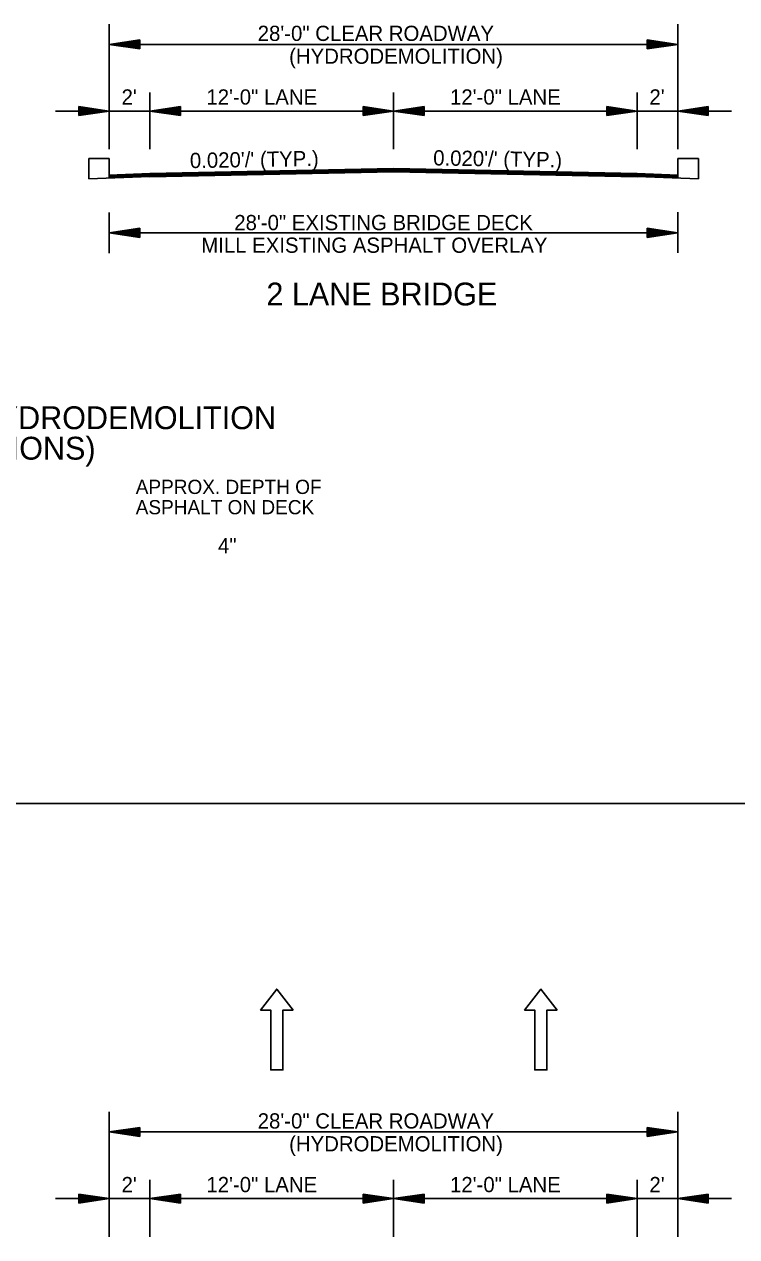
# Model space of a CAD drawing. Extents: x 549600 to 1930787, y -1955432 to 596640.
# Drawn here: x 551680 to 552031, y -1952647 to -1952050 of the extents above; entities that cross this region are included whole.
import ezdxf

# ---------------------------------------------------------------- set-up
doc = ezdxf.new("R2010")
doc.units = 0
for name, color, linetype in [('R_Border', 7, 'Continuous'), ('R_Border Notes', 7, 'Continuous'), ('S_AREA_CALC', 7, 'Continuous')]:
    doc.layers.add(name, color=color, linetype=linetype)

msp = doc.modelspace()

# ---------------------------------------------------------------- linework, layer by layer
at = {"layer": 'R_Border'}
for p, q in [((551711.85, -1952115.83), (551711.85, -1952125.95)), ((551722.02, -1952115.83), (551711.85, -1952115.83)), ((551722.02, -1952125.24), (551722.02, -1952115.83)), ((552002.02, -1952125.24), (552002.02, -1952115.83)), ((552002.02, -1952115.83), (552012.18, -1952115.83)), ((552012.18, -1952115.83), (552012.18, -1952125.95)), ((551008.97, -1952433.38), (552070.24, -1952433.38))]:
    msp.add_line(p, q, dxfattribs=at)
for points in [[(551812.52, -1952535.08), (551804.52, -1952524.69), (551796.52, -1952535.08), (551801.52, -1952535.08), (551801.52, -1952564.5), (551807.52, -1952564.5), (551807.52, -1952535.08)], [(551942.58, -1952535.08), (551934.58, -1952524.69), (551926.58, -1952535.08), (551931.58, -1952535.08), (551931.58, -1952564.5), (551937.58, -1952564.5), (551937.58, -1952535.08)]]:
    msp.add_lwpolyline(points, close=True, dxfattribs=at)
at = {"layer": 'S_AREA_CALC'}
for p, q in [((551722.02, -1952111.3), (551722.02, -1952049.81)), ((552002.02, -1952111.3), (552002.02, -1952049.81)), ((551737.02, -1952057.45), (551722.02, -1952059.7)), ((552002.02, -1952059.7), (551722.02, -1952059.7)), ((551737.02, -1952061.95), (551722.02, -1952059.7)), ((551737.02, -1952057.82), (551724.52, -1952059.7)), ((551737.02, -1952061.57), (551724.52, -1952059.7)), ((551737.02, -1952058.21), (551727.1, -1952059.7)), ((551737.02, -1952061.19), (551727.1, -1952059.7)), ((551737.02, -1952058.58), (551729.6, -1952059.7)), ((551737.02, -1952060.82), (551729.6, -1952059.7)), ((551737.02, -1952058.97), (551732.14, -1952059.7)), ((551737.02, -1952060.43), (551732.14, -1952059.7)), ((551737.02, -1952059.35), (551734.65, -1952059.7)), ((551737.02, -1952060.05), (551734.65, -1952059.7)), ((551737.02, -1952057.45), (551737.02, -1952061.95)), ((551987.02, -1952057.45), (552002.02, -1952059.7)), ((551987.02, -1952061.95), (551987.02, -1952057.45)), ((551987.02, -1952057.82), (551999.51, -1952059.7)), ((551987.02, -1952058.21), (551996.93, -1952059.7)), ((551987.02, -1952058.58), (551994.44, -1952059.7)), ((551987.02, -1952058.96), (551991.89, -1952059.7)), ((551987.02, -1952059.35), (551989.39, -1952059.7)), ((551987.02, -1952061.95), (552002.02, -1952059.7)), ((551987.02, -1952060.43), (551991.89, -1952059.7)), ((551987.02, -1952061.19), (551996.93, -1952059.7)), ((551987.02, -1952061.57), (551999.51, -1952059.7)), ((551987.02, -1952060.82), (551994.44, -1952059.7)), ((551987.02, -1952060.05), (551989.39, -1952059.7)), ((551742.02, -1952111.3), (551742.02, -1952083.34)), ((551862.02, -1952111.3), (551862.02, -1952083.34)), ((551982.02, -1952111.3), (551982.02, -1952083.34)), ((551722.02, -1952092.53), (551695.5, -1952092.53)), ((551707.02, -1952090.28), (551722.02, -1952092.53)), ((551707.02, -1952090.28), (551707.02, -1952094.78)), ((551707.02, -1952090.66), (551719.51, -1952092.53)), ((551707.02, -1952091.04), (551716.93, -1952092.53)), ((551707.02, -1952091.42), (551714.44, -1952092.53)), ((551707.02, -1952091.81), (551711.89, -1952092.53)), ((551707.02, -1952092.18), (551709.39, -1952092.53)), ((551707.02, -1952094.78), (551722.02, -1952092.53)), ((551707.02, -1952093.27), (551711.89, -1952092.53)), ((551707.02, -1952094.03), (551716.93, -1952092.53)), ((551707.02, -1952094.41), (551719.51, -1952092.53)), ((551707.02, -1952093.65), (551714.44, -1952092.53)), ((551707.02, -1952092.89), (551709.39, -1952092.53)), ((551742.02, -1952092.53), (551722.02, -1952092.53)), ((551757.02, -1952090.28), (551742.02, -1952092.53)), ((551862.02, -1952092.53), (551742.02, -1952092.53)), ((551757.02, -1952094.78), (551742.02, -1952092.53)), ((551757.02, -1952090.66), (551744.52, -1952092.53)), ((551757.02, -1952094.41), (551744.52, -1952092.53)), ((551757.02, -1952091.04), (551747.1, -1952092.53)), ((551757.02, -1952094.03), (551747.1, -1952092.53)), ((551757.02, -1952091.42), (551749.6, -1952092.53)), ((551757.02, -1952093.65), (551749.6, -1952092.53)), ((551757.02, -1952091.81), (551752.14, -1952092.53)), ((551757.02, -1952093.27), (551752.14, -1952092.53)), ((551757.02, -1952092.18), (551754.65, -1952092.53)), ((551757.02, -1952092.89), (551754.65, -1952092.53)), ((551757.02, -1952090.28), (551757.02, -1952094.78)), ((551847.02, -1952090.28), (551862.02, -1952092.53)), ((551847.02, -1952090.28), (551847.02, -1952094.78)), ((551847.02, -1952090.66), (551859.51, -1952092.53)), ((551847.02, -1952091.04), (551856.93, -1952092.53)), ((551847.02, -1952091.42), (551854.44, -1952092.53)), ((551847.02, -1952091.81), (551851.89, -1952092.53)), ((551847.02, -1952092.18), (551849.39, -1952092.53)), ((551847.02, -1952094.78), (551862.02, -1952092.53)), ((551847.02, -1952093.27), (551851.89, -1952092.53)), ((551847.02, -1952094.03), (551856.93, -1952092.53)), ((551847.02, -1952094.41), (551859.51, -1952092.53)), ((551847.02, -1952093.65), (551854.44, -1952092.53)), ((551847.02, -1952092.89), (551849.39, -1952092.53)), ((551877.02, -1952090.28), (551862.02, -1952092.53)), ((551982.02, -1952092.53), (551862.02, -1952092.53)), ((551877.02, -1952094.78), (551862.02, -1952092.53)), ((551877.02, -1952090.66), (551864.52, -1952092.53)), ((551877.02, -1952094.41), (551864.52, -1952092.53)), ((551877.02, -1952091.04), (551867.1, -1952092.53)), ((551877.02, -1952094.03), (551867.1, -1952092.53)), ((551877.02, -1952091.42), (551869.6, -1952092.53)), ((551877.02, -1952093.65), (551869.6, -1952092.53)), ((551877.02, -1952091.81), (551872.14, -1952092.53)), ((551877.02, -1952093.27), (551872.14, -1952092.53)), ((551877.02, -1952092.18), (551874.65, -1952092.53)), ((551877.02, -1952092.89), (551874.65, -1952092.53)), ((551877.02, -1952090.28), (551877.02, -1952094.78)), ((551967.02, -1952090.28), (551982.02, -1952092.53)), ((551967.02, -1952090.28), (551967.02, -1952094.78)), ((551967.02, -1952090.66), (551979.51, -1952092.53)), ((551967.02, -1952091.04), (551976.93, -1952092.53)), ((551967.02, -1952091.42), (551974.44, -1952092.53)), ((551967.02, -1952091.81), (551971.89, -1952092.53)), ((551967.02, -1952092.18), (551969.39, -1952092.53)), ((551967.02, -1952094.78), (551982.02, -1952092.53)), ((551967.02, -1952093.27), (551971.89, -1952092.53)), ((551967.02, -1952094.03), (551976.93, -1952092.53)), ((551967.02, -1952094.41), (551979.51, -1952092.53)), ((551967.02, -1952093.65), (551974.44, -1952092.53)), ((551967.02, -1952092.89), (551969.39, -1952092.53)), ((551982.02, -1952092.53), (552002.02, -1952092.53)), ((552017.02, -1952090.28), (552002.02, -1952092.53)), ((552017.02, -1952094.78), (552002.02, -1952092.53)), ((552028.54, -1952092.53), (552002.02, -1952092.53)), ((552017.02, -1952090.66), (552004.52, -1952092.53)), ((552017.02, -1952094.41), (552004.52, -1952092.53)), ((552017.02, -1952091.04), (552007.1, -1952092.53)), ((552017.02, -1952094.03), (552007.1, -1952092.53)), ((552017.02, -1952091.42), (552009.6, -1952092.53)), ((552017.02, -1952093.65), (552009.6, -1952092.53)), ((552017.02, -1952091.81), (552012.14, -1952092.53)), ((552017.02, -1952093.27), (552012.14, -1952092.53)), ((552017.02, -1952092.18), (552014.65, -1952092.53)), ((552017.02, -1952092.89), (552014.65, -1952092.53)), ((552017.02, -1952090.28), (552017.02, -1952094.78)), ((551862.02, -1952120.84), (551742.02, -1952123.24)), ((551862.02, -1952121.14), (551742.02, -1952123.54)), ((551862.02, -1952121.44), (551742.02, -1952123.84)), ((551862.02, -1952121.74), (551742.02, -1952124.14)), ((551862.02, -1952122.04), (551742.02, -1952124.44)), ((551862.02, -1952122.34), (551742.02, -1952124.74)), ((551862.02, -1952122.51), (551742.02, -1952124.91)), ((551862.02, -1952120.84), (551982.02, -1952123.24)), ((551862.02, -1952121.14), (551982.02, -1952123.54)), ((551862.02, -1952121.44), (551982.02, -1952123.84)), ((551862.02, -1952121.74), (551982.02, -1952124.14)), ((551862.02, -1952122.04), (551982.02, -1952124.44)), ((551862.02, -1952122.34), (551982.02, -1952124.74)), ((551862.02, -1952122.51), (551982.02, -1952124.91)), ((551742.02, -1952124.74), (551711.85, -1952125.95)), ((551742.02, -1952123.24), (551722.02, -1952124.04)), ((551742.02, -1952123.54), (551722.02, -1952124.34)), ((551742.02, -1952123.84), (551722.02, -1952124.64)), ((551742.02, -1952124.14), (551722.02, -1952124.94)), ((551742.02, -1952124.44), (551722.02, -1952125.24)), ((551982.02, -1952123.24), (552002.02, -1952124.04)), ((551982.02, -1952123.54), (552002.02, -1952124.34)), ((551982.02, -1952123.84), (552002.02, -1952124.64)), ((551982.02, -1952124.14), (552002.02, -1952124.94)), ((551982.02, -1952124.44), (552002.02, -1952125.24)), ((551982.02, -1952124.74), (552012.18, -1952125.95)), ((551722.02, -1952142.5), (551722.02, -1952162.5)), ((552002.02, -1952142.25), (552002.02, -1952162.25)), ((551737.02, -1952150.25), (551722.02, -1952152.5)), ((551737.02, -1952154.75), (551722.02, -1952152.5)), ((552002.02, -1952152.5), (551722.02, -1952152.5)), ((551737.02, -1952150.63), (551724.52, -1952152.5)), ((551737.02, -1952154.38), (551724.52, -1952152.5)), ((551737.02, -1952151.01), (551727.1, -1952152.5)), ((551737.02, -1952153.99), (551727.1, -1952152.5)), ((551737.02, -1952151.38), (551729.6, -1952152.5)), ((551737.02, -1952153.62), (551729.6, -1952152.5)), ((551737.02, -1952151.77), (551732.14, -1952152.5)), ((551737.02, -1952153.24), (551732.14, -1952152.5)), ((551737.02, -1952152.15), (551734.65, -1952152.5)), ((551737.02, -1952152.85), (551734.65, -1952152.5)), ((551737.02, -1952150.25), (551737.02, -1952154.75)), ((551987.02, -1952150.25), (552002.02, -1952152.5)), ((551987.02, -1952154.75), (551987.02, -1952150.25)), ((551987.02, -1952150.63), (551999.51, -1952152.5)), ((551987.02, -1952151.01), (551996.93, -1952152.5)), ((551987.02, -1952151.38), (551994.44, -1952152.5)), ((551987.02, -1952151.77), (551991.89, -1952152.5)), ((551987.02, -1952152.15), (551989.39, -1952152.5)), ((551987.02, -1952154.75), (552002.02, -1952152.5)), ((551987.02, -1952153.23), (551991.89, -1952152.5)), ((551987.02, -1952153.99), (551996.93, -1952152.5)), ((551987.02, -1952154.38), (551999.51, -1952152.5)), ((551987.02, -1952153.62), (551994.44, -1952152.5)), ((551987.02, -1952152.85), (551989.39, -1952152.5)), ((551722.02, -1952646.64), (551722.02, -1952585.15)), ((552002.02, -1952646.64), (552002.02, -1952585.15)), ((551737.02, -1952592.79), (551722.02, -1952595.04)), ((551737.02, -1952593.17), (551724.52, -1952595.04)), ((551737.02, -1952593.55), (551727.1, -1952595.04)), ((551737.02, -1952593.92), (551729.6, -1952595.04)), ((551737.02, -1952594.31), (551732.14, -1952595.04)), ((551737.02, -1952592.79), (551737.02, -1952597.29)), ((551987.02, -1952592.79), (552002.02, -1952595.04)), ((551987.02, -1952597.29), (551987.02, -1952592.79)), ((551987.02, -1952593.17), (551999.51, -1952595.04)), ((551987.02, -1952593.55), (551996.93, -1952595.04)), ((551987.02, -1952593.92), (551994.44, -1952595.04)), ((551987.02, -1952594.31), (551991.89, -1952595.04)), ((552002.02, -1952595.04), (551722.02, -1952595.04)), ((551737.02, -1952597.29), (551722.02, -1952595.04)), ((551737.02, -1952596.92), (551724.52, -1952595.04)), ((551737.02, -1952596.53), (551727.1, -1952595.04)), ((551737.02, -1952596.16), (551729.6, -1952595.04)), ((551737.02, -1952595.78), (551732.14, -1952595.04)), ((551737.02, -1952594.69), (551734.65, -1952595.04)), ((551737.02, -1952595.39), (551734.65, -1952595.04)), ((551987.02, -1952594.69), (551989.39, -1952595.04)), ((551987.02, -1952597.29), (552002.02, -1952595.04)), ((551987.02, -1952595.77), (551991.89, -1952595.04)), ((551987.02, -1952596.53), (551996.93, -1952595.04)), ((551987.02, -1952596.92), (551999.51, -1952595.04)), ((551987.02, -1952596.16), (551994.44, -1952595.04)), ((551987.02, -1952595.39), (551989.39, -1952595.04)), ((551742.02, -1952646.64), (551742.02, -1952618.69)), ((551862.02, -1952646.64), (551862.02, -1952618.69)), ((551982.02, -1952646.64), (551982.02, -1952618.69)), ((551722.02, -1952627.88), (551695.5, -1952627.88)), ((551707.02, -1952625.63), (551722.02, -1952627.88)), ((551707.02, -1952625.63), (551707.02, -1952630.13)), ((551707.02, -1952626), (551719.51, -1952627.88)), ((551707.02, -1952626.38), (551716.93, -1952627.88)), ((551707.02, -1952626.76), (551714.44, -1952627.88)), ((551707.02, -1952627.15), (551711.89, -1952627.88)), ((551707.02, -1952627.52), (551709.39, -1952627.88)), ((551707.02, -1952630.13), (551722.02, -1952627.88)), ((551707.02, -1952628.61), (551711.89, -1952627.88)), ((551707.02, -1952629.37), (551716.93, -1952627.88)), ((551707.02, -1952629.75), (551719.51, -1952627.88)), ((551707.02, -1952628.99), (551714.44, -1952627.88)), ((551707.02, -1952628.23), (551709.39, -1952627.88)), ((551742.02, -1952627.88), (551722.02, -1952627.88)), ((551757.02, -1952625.63), (551742.02, -1952627.88)), ((551862.02, -1952627.88), (551742.02, -1952627.88)), ((551757.02, -1952630.13), (551742.02, -1952627.88)), ((551757.02, -1952626), (551744.52, -1952627.88)), ((551757.02, -1952629.75), (551744.52, -1952627.88)), ((551757.02, -1952626.38), (551747.1, -1952627.88)), ((551757.02, -1952629.37), (551747.1, -1952627.88)), ((551757.02, -1952626.76), (551749.6, -1952627.88)), ((551757.02, -1952628.99), (551749.6, -1952627.88)), ((551757.02, -1952627.15), (551752.14, -1952627.88)), ((551757.02, -1952628.61), (551752.14, -1952627.88)), ((551757.02, -1952627.52), (551754.65, -1952627.88)), ((551757.02, -1952628.23), (551754.65, -1952627.88)), ((551757.02, -1952625.63), (551757.02, -1952630.13)), ((551847.02, -1952625.63), (551862.02, -1952627.88)), ((551847.02, -1952625.63), (551847.02, -1952630.13)), ((551847.02, -1952626), (551859.51, -1952627.88)), ((551847.02, -1952626.38), (551856.93, -1952627.88)), ((551847.02, -1952626.76), (551854.44, -1952627.88)), ((551847.02, -1952627.15), (551851.89, -1952627.88)), ((551847.02, -1952627.52), (551849.39, -1952627.88)), ((551847.02, -1952630.13), (551862.02, -1952627.88)), ((551847.02, -1952628.61), (551851.89, -1952627.88)), ((551847.02, -1952629.37), (551856.93, -1952627.88)), ((551847.02, -1952629.75), (551859.51, -1952627.88)), ((551847.02, -1952628.99), (551854.44, -1952627.88)), ((551847.02, -1952628.23), (551849.39, -1952627.88)), ((551877.02, -1952625.63), (551862.02, -1952627.88)), ((551982.02, -1952627.88), (551862.02, -1952627.88)), ((551877.02, -1952630.13), (551862.02, -1952627.88)), ((551877.02, -1952626), (551864.52, -1952627.88)), ((551877.02, -1952629.75), (551864.52, -1952627.88)), ((551877.02, -1952626.38), (551867.1, -1952627.88)), ((551877.02, -1952629.37), (551867.1, -1952627.88)), ((551877.02, -1952626.76), (551869.6, -1952627.88)), ((551877.02, -1952628.99), (551869.6, -1952627.88)), ((551877.02, -1952627.15), (551872.14, -1952627.88)), ((551877.02, -1952628.61), (551872.14, -1952627.88)), ((551877.02, -1952627.52), (551874.65, -1952627.88)), ((551877.02, -1952628.23), (551874.65, -1952627.88)), ((551877.02, -1952625.63), (551877.02, -1952630.13)), ((551967.02, -1952625.63), (551982.02, -1952627.88)), ((551967.02, -1952625.63), (551967.02, -1952630.13)), ((551967.02, -1952626), (551979.51, -1952627.88)), ((551967.02, -1952626.38), (551976.93, -1952627.88)), ((551967.02, -1952626.76), (551974.44, -1952627.88)), ((551967.02, -1952627.15), (551971.89, -1952627.88)), ((551967.02, -1952627.52), (551969.39, -1952627.88)), ((551967.02, -1952630.13), (551982.02, -1952627.88)), ((551967.02, -1952628.61), (551971.89, -1952627.88)), ((551967.02, -1952629.37), (551976.93, -1952627.88)), ((551967.02, -1952629.75), (551979.51, -1952627.88)), ((551967.02, -1952628.99), (551974.44, -1952627.88)), ((551967.02, -1952628.23), (551969.39, -1952627.88)), ((551982.02, -1952627.88), (552002.02, -1952627.88)), ((552017.02, -1952625.63), (552002.02, -1952627.88)), ((552017.02, -1952630.13), (552002.02, -1952627.88)), ((552028.54, -1952627.88), (552002.02, -1952627.88)), ((552017.02, -1952626), (552004.52, -1952627.88)), ((552017.02, -1952629.75), (552004.52, -1952627.88)), ((552017.02, -1952626.38), (552007.1, -1952627.88)), ((552017.02, -1952629.37), (552007.1, -1952627.88)), ((552017.02, -1952626.76), (552009.6, -1952627.88)), ((552017.02, -1952628.99), (552009.6, -1952627.88)), ((552017.02, -1952627.15), (552012.14, -1952627.88)), ((552017.02, -1952628.61), (552012.14, -1952627.88)), ((552017.02, -1952627.52), (552014.65, -1952627.88)), ((552017.02, -1952628.23), (552014.65, -1952627.88)), ((552017.02, -1952625.63), (552017.02, -1952630.13))]:
    msp.add_line(p, q, dxfattribs=at)

# ---------------------------------------------------------------- texts
at = {"layer": 'R_Border'}
for s, height, p in [('28 FT. CLEAR ROADWAY BRIDGE - HYDRODEMOLITION', 11.25, (551401.23, -1952249.12)), ('(ROADWAY TRANSITIONS)', 11.25, (551522.18, -1952264.12)), ('4"', 7.5, (551775.54, -1952310.2))]:
    msp.add_text(s, height=height, dxfattribs=at).set_placement(p)
at = {"layer": 'R_Border Notes'}
for s, p in [('APPROX. DEPTH OF', (551735.02, -1952281.02)), ('ASPHALT ON DECK', (551735.02, -1952291.02))]:
    msp.add_text(s, height=7, dxfattribs=at).set_placement(p)
at = {"layer": 'S_AREA_CALC'}
for s, height, p in [('28\'-0" CLEAR ROADWAY', 7.5, (551795.11, -1952058.03)), ('(HYDRODEMOLITION)', 7.5, (551810.58, -1952069.28)), ("2'", 7.5, (551728.06, -1952089.36)), ('12\'-0" LANE', 7.5, (551769.84, -1952089.36)), ('12\'-0" LANE', 7.5, (551889.84, -1952089.36)), ("2'", 7.5, (551988.06, -1952089.36)), ('28\'-0" EXISTING BRIDGE DECK', 7.5, (551783.57, -1952151.18)), ('MILL EXISTING ASPHALT OVERLAY', 7.5, (551767.29, -1952162.31)), ('2 LANE BRIDGE', 11.25, (551799.39, -1952188.22)), ('28\'-0" CLEAR ROADWAY', 7.5, (551795.11, -1952593.37)), ('(HYDRODEMOLITION)', 7.5, (551810.58, -1952604.62)), ("2'", 7.5, (551728.06, -1952624.71)), ('12\'-0" LANE', 7.5, (551769.84, -1952624.71)), ('12\'-0" LANE', 7.5, (551889.84, -1952624.71)), ("2'", 7.5, (551988.06, -1952624.71))]:
    msp.add_text(s, height=height, dxfattribs=at).set_placement(p)
for rotation, p in [(0.97192, (551761.76, -1952120.64)), (359.02808, (551881.5, -1952119.27))]:
    msp.add_text("0.020'/' (TYP.)", height=7.5, rotation=rotation, dxfattribs=at).set_placement(p)

doc.saveas('drawing.dxf')
